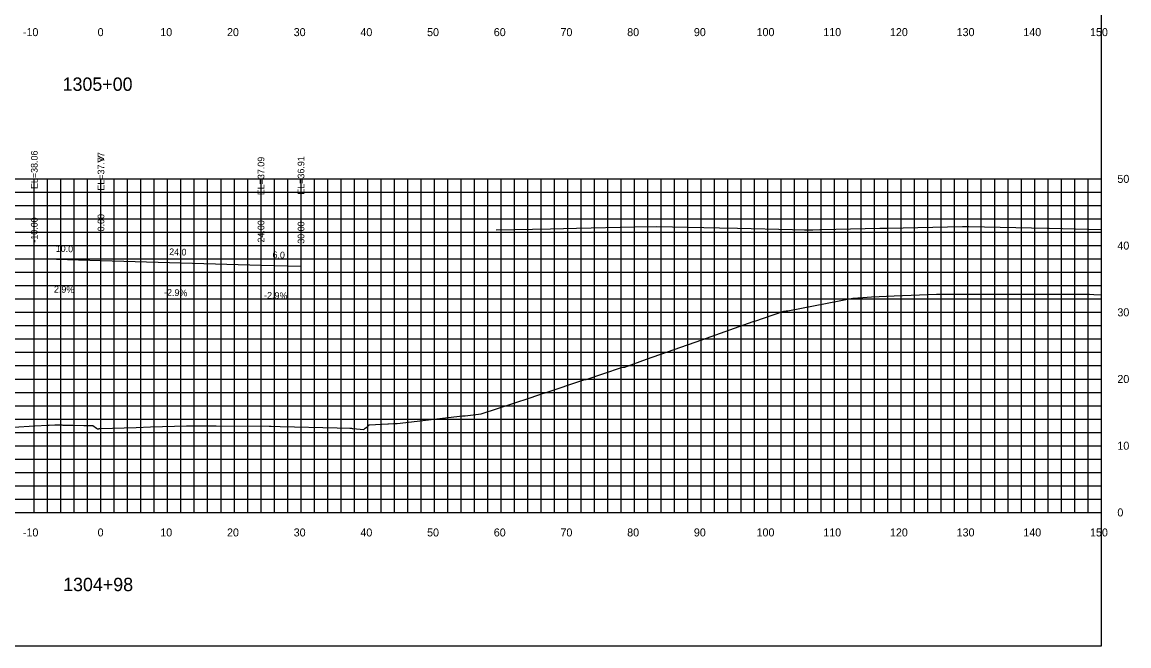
# Model space of a CAD drawing. Extents: x 1797714 to 1804825, y 249015 to 250269.
# Drawn here: x 1803952.3 to 1804118.3, y 249628.2 to 249721.7 of the extents above; entities that cross this region are included whole.
import ezdxf

# ---------------------------------------------------------------- set-up
doc = ezdxf.new("R2010")
doc.units = 0
for name, color, linetype in [('1', 7, 'Continuous'), ('10', 7, 'Continuous'), ('3', 7, 'Continuous'), ('31', 7, 'Continuous'), ('4', 7, 'Continuous'), ('60', 7, 'Continuous'), ('CL-CNST', 7, 'Continuous'), ('Level 62', 7, 'Continuous'), ('M-ROADS', 7, 'Continuous'), ('WEARING', 7, 'Continuous')]:
    doc.layers.add(name, color=color, linetype=linetype)

msp = doc.modelspace()

# ---------------------------------------------------------------- linework, layer by layer
for p, q in [((1803954.16, 249686.23), (1803954.16, 249688.23)), ((1803964.16, 249685.94), (1803964.16, 249687.94)), ((1803988.16, 249685.25), (1803988.16, 249687.25)), ((1803994.16, 249685.08), (1803994.16, 249687.08))]:
    msp.add_line(p, q)
msp.add_lwpolyline([(1803814.16, 249628.17), (1804114.16, 249628.17), (1804114.16, 249818.17), (1803814.16, 249818.17)], close=True)
at = {"layer": '60'}
for p, q in [((1804114.16, 249648.17), (1804114.16, 249698.17)), ((1804114.22, 249698.17), (1804114.16, 249698.17)), ((1804114.22, 249688.17), (1804114.16, 249688.17)), ((1804114.22, 249678.17), (1804114.16, 249678.17)), ((1804114.22, 249668.17), (1804114.16, 249668.17)), ((1804114.22, 249658.17), (1804114.16, 249658.17)), ((1803814.16, 249648.17), (1804114.16, 249648.17)), ((1803954.16, 249648.11), (1803954.16, 249648.17)), ((1803964.16, 249648.11), (1803964.16, 249648.17)), ((1803974.16, 249648.11), (1803974.16, 249648.17)), ((1803984.16, 249648.11), (1803984.16, 249648.17)), ((1803994.16, 249648.11), (1803994.16, 249648.17)), ((1804004.16, 249648.11), (1804004.16, 249648.17)), ((1804014.16, 249648.11), (1804014.16, 249648.17)), ((1804024.16, 249648.11), (1804024.16, 249648.17)), ((1804034.16, 249648.11), (1804034.16, 249648.17)), ((1804044.16, 249648.11), (1804044.16, 249648.17)), ((1804054.16, 249648.11), (1804054.16, 249648.17)), ((1804064.16, 249648.11), (1804064.16, 249648.17)), ((1804074.16, 249648.11), (1804074.16, 249648.17)), ((1804084.16, 249648.11), (1804084.16, 249648.17)), ((1804094.16, 249648.11), (1804094.16, 249648.17)), ((1804104.16, 249648.11), (1804104.16, 249648.17)), ((1804114.16, 249648.11), (1804114.16, 249648.17)), ((1804114.22, 249648.17), (1804114.16, 249648.17))]:
    msp.add_line(p, q, dxfattribs=at)
at = {"layer": 'CL-CNST'}
for points in [[(1804023.41, 249690.52), (1804031.56, 249690.7), (1804035.47, 249690.78), (1804044.23, 249690.97), (1804047.53, 249691.04), (1804056.91, 249690.83), (1804059.59, 249690.77), (1804067.85, 249690.59), (1804069.64, 249690.55), (1804070.69, 249690.52), (1804070.9, 249690.52)], [(1803954.16, 249686.23), (1803964.16, 249685.94), (1803988.16, 249685.25), (1803994.16, 249685.08)]]:
    msp.add_lwpolyline(points, dxfattribs=at)
at = {"layer": 'Level 62'}
for p, q in [((1803814.16, 249698.17), (1804114.16, 249698.17)), ((1803954.16, 249648.17), (1803954.16, 249698.17)), ((1803956.16, 249648.17), (1803956.16, 249698.17)), ((1803958.16, 249648.17), (1803958.16, 249698.17)), ((1803960.16, 249648.17), (1803960.16, 249698.17)), ((1803962.16, 249648.17), (1803962.16, 249698.17)), ((1803964.16, 249648.17), (1803964.16, 249698.17)), ((1803966.16, 249648.17), (1803966.16, 249698.17)), ((1803968.16, 249648.17), (1803968.16, 249698.17)), ((1803970.16, 249648.17), (1803970.16, 249698.17)), ((1803972.16, 249648.17), (1803972.16, 249698.17)), ((1803974.16, 249648.17), (1803974.16, 249698.17)), ((1803976.16, 249648.17), (1803976.16, 249698.17)), ((1803978.16, 249648.17), (1803978.16, 249698.17)), ((1803980.16, 249648.17), (1803980.16, 249698.17)), ((1803982.16, 249648.17), (1803982.16, 249698.17)), ((1803984.16, 249648.17), (1803984.16, 249698.17)), ((1803986.16, 249648.17), (1803986.16, 249698.17)), ((1803988.16, 249648.17), (1803988.16, 249698.17)), ((1803990.16, 249648.17), (1803990.16, 249698.17)), ((1803992.16, 249648.17), (1803992.16, 249698.17)), ((1803994.16, 249648.17), (1803994.16, 249698.17)), ((1803996.16, 249648.17), (1803996.16, 249698.17)), ((1803998.16, 249648.17), (1803998.16, 249698.17)), ((1804000.16, 249648.17), (1804000.16, 249698.17)), ((1804002.16, 249648.17), (1804002.16, 249698.17)), ((1804004.16, 249648.17), (1804004.16, 249698.17)), ((1804006.16, 249648.17), (1804006.16, 249698.17)), ((1804008.16, 249648.17), (1804008.16, 249698.17)), ((1804010.16, 249648.17), (1804010.16, 249698.17)), ((1804012.16, 249648.17), (1804012.16, 249698.17)), ((1804014.16, 249648.17), (1804014.16, 249698.17)), ((1804016.16, 249648.17), (1804016.16, 249698.17)), ((1804018.16, 249648.17), (1804018.16, 249698.17)), ((1804020.16, 249648.17), (1804020.16, 249698.17)), ((1804022.16, 249648.17), (1804022.16, 249698.17)), ((1804024.16, 249648.17), (1804024.16, 249698.17)), ((1804026.16, 249648.17), (1804026.16, 249698.17)), ((1804028.16, 249648.17), (1804028.16, 249698.17)), ((1804030.16, 249648.17), (1804030.16, 249698.17)), ((1804032.16, 249648.17), (1804032.16, 249698.17)), ((1804034.16, 249648.17), (1804034.16, 249698.17)), ((1804036.16, 249648.17), (1804036.16, 249698.17)), ((1804038.16, 249648.17), (1804038.16, 249698.17)), ((1804040.16, 249648.17), (1804040.16, 249698.17)), ((1804042.16, 249648.17), (1804042.16, 249698.17)), ((1804044.16, 249648.17), (1804044.16, 249698.17)), ((1804046.16, 249648.17), (1804046.16, 249698.17)), ((1804048.16, 249648.17), (1804048.16, 249698.17)), ((1804050.16, 249648.17), (1804050.16, 249698.17)), ((1804052.16, 249648.17), (1804052.16, 249698.17)), ((1804054.16, 249648.17), (1804054.16, 249698.17)), ((1804056.16, 249648.17), (1804056.16, 249698.17)), ((1804058.16, 249648.17), (1804058.16, 249698.17)), ((1804060.16, 249648.17), (1804060.16, 249698.17)), ((1804062.16, 249648.17), (1804062.16, 249698.17)), ((1804064.16, 249648.17), (1804064.16, 249698.17)), ((1804066.16, 249648.17), (1804066.16, 249698.17)), ((1804068.16, 249648.17), (1804068.16, 249698.17)), ((1804070.16, 249648.17), (1804070.16, 249698.17)), ((1804072.16, 249648.17), (1804072.16, 249698.17)), ((1804074.16, 249648.17), (1804074.16, 249698.17)), ((1804076.16, 249648.17), (1804076.16, 249698.17)), ((1804078.16, 249648.17), (1804078.16, 249698.17)), ((1804080.16, 249648.17), (1804080.16, 249698.17)), ((1804082.16, 249648.17), (1804082.16, 249698.17)), ((1804084.16, 249648.17), (1804084.16, 249698.17)), ((1804086.16, 249648.17), (1804086.16, 249698.17)), ((1804088.16, 249648.17), (1804088.16, 249698.17)), ((1804090.16, 249648.17), (1804090.16, 249698.17)), ((1804092.16, 249648.17), (1804092.16, 249698.17)), ((1804094.16, 249648.17), (1804094.16, 249698.17)), ((1804096.16, 249648.17), (1804096.16, 249698.17)), ((1804098.16, 249648.17), (1804098.16, 249698.17)), ((1804100.16, 249648.17), (1804100.16, 249698.17)), ((1804102.16, 249648.17), (1804102.16, 249698.17)), ((1804104.16, 249648.17), (1804104.16, 249698.17)), ((1804106.16, 249648.17), (1804106.16, 249698.17)), ((1804108.16, 249648.17), (1804108.16, 249698.17)), ((1804110.16, 249648.17), (1804110.16, 249698.17)), ((1804112.16, 249648.17), (1804112.16, 249698.17)), ((1804114.16, 249648.17), (1804114.16, 249698.17)), ((1803814.16, 249696.17), (1804114.16, 249696.17)), ((1803814.16, 249694.17), (1804114.16, 249694.17)), ((1803814.16, 249692.17), (1804114.16, 249692.17)), ((1803814.16, 249690.17), (1804114.16, 249690.17)), ((1803814.16, 249688.17), (1804114.16, 249688.17)), ((1803814.16, 249686.17), (1804114.16, 249686.17)), ((1803814.16, 249684.17), (1804114.16, 249684.17)), ((1803814.16, 249682.17), (1804114.16, 249682.17)), ((1803814.16, 249680.17), (1804114.16, 249680.17)), ((1803814.16, 249678.17), (1804114.16, 249678.17)), ((1803814.16, 249676.17), (1804114.16, 249676.17)), ((1803814.16, 249674.17), (1804114.16, 249674.17)), ((1803814.16, 249672.17), (1804114.16, 249672.17)), ((1803814.16, 249670.17), (1804114.16, 249670.17)), ((1803814.16, 249668.17), (1804114.16, 249668.17)), ((1803814.16, 249666.17), (1804114.16, 249666.17)), ((1803814.16, 249664.17), (1804114.16, 249664.17)), ((1803814.16, 249662.17), (1804114.16, 249662.17)), ((1803814.16, 249660.17), (1804114.16, 249660.17)), ((1803814.16, 249658.17), (1804114.16, 249658.17)), ((1803814.16, 249656.17), (1804114.16, 249656.17)), ((1803814.16, 249654.17), (1804114.16, 249654.17)), ((1803814.16, 249652.17), (1804114.16, 249652.17)), ((1803814.16, 249650.17), (1804114.16, 249650.17)), ((1803814.16, 249648.17), (1804114.16, 249648.17))]:
    msp.add_line(p, q, dxfattribs=at)
at = {"layer": 'M-ROADS'}
msp.add_lwpolyline([(1803951.12, 249660.96), (1803954.14, 249661.16), (1803954.25, 249661.17), (1803956.18, 249661.25), (1803956.42, 249661.26), (1803957.23, 249661.3), (1803957.3, 249661.3), (1803957.74, 249661.3), (1803958.3, 249661.28), (1803958.46, 249661.27), (1803959.9, 249661.23), (1803959.96, 249661.23), (1803961.6, 249661.22), (1803962.14, 249661.2), (1803962.95, 249661.19), (1803963.49, 249660.78), (1803963.59, 249660.72), (1803963.79, 249660.72), (1803963.8, 249660.72), (1803963.81, 249660.72), (1803963.83, 249660.72), (1803963.85, 249660.73), (1803963.87, 249660.73), (1803963.9, 249660.73), (1803963.94, 249660.73), (1803963.99, 249660.73), (1803964.05, 249660.74), (1803964.11, 249660.74), (1803969.44, 249660.92), (1803971.58, 249660.99), (1803976.98, 249661.17), (1803977.33, 249661.16), (1803977.39, 249661.16), (1803981.45, 249661.14), (1803989.39, 249661.1), (1803989.69, 249661.09), (1803991.04, 249661.06), (1803999.58, 249660.85), (1804001.5, 249660.8), (1804001.61, 249660.79), (1804001.73, 249660.78), (1804001.83, 249660.77), (1804001.93, 249660.76), (1804003.56, 249660.59), (1804003.78, 249660.78), (1804004.16, 249661.06), (1804004.26, 249661.19), (1804004.37, 249661.28), (1804004.4, 249661.29), (1804007.17, 249661.43), (1804007.28, 249661.44), (1804008.02, 249661.5), (1804008.47, 249661.5), (1804008.56, 249661.5), (1804018.37, 249662.64), (1804018.47, 249662.65), (1804018.78, 249662.64), (1804021.15, 249662.94), (1804028.53, 249665.35), (1804030.66, 249666.08), (1804030.77, 249666.08), (1804036.58, 249668.06), (1804036.89, 249668.08), (1804042.19, 249669.92), (1804042.49, 249669.93), (1804042.7, 249669.93), (1804045.94, 249671.13), (1804054.25, 249674.04), (1804061.96, 249676.78), (1804062.06, 249676.78), (1804066.56, 249678.35), (1804066.92, 249678.37), (1804067.14, 249678.38), (1804076.88, 249680.28), (1804078.37, 249680.4), (1804079.7, 249680.51), (1804083.09, 249680.63), (1804089.42, 249680.89), (1804094.01, 249680.9), (1804100.81, 249680.9), (1804109.34, 249680.9), (1804112.39, 249680.9), (1804113.05, 249680.85), (1804114.16, 249680.77)], dxfattribs=at)
at = {"layer": 'WEARING'}
msp.add_lwpolyline([(1804070.9, 249690.55), (1804071.95, 249690.57), (1804072.16, 249690.57), (1804080.94, 249690.76), (1804082.21, 249690.79), (1804093.35, 249691.02), (1804094.27, 249691.04), (1804106.02, 249690.78), (1804106.33, 249690.77), (1804112.29, 249690.64), (1804114.16, 249690.6)], dxfattribs=at)

# ---------------------------------------------------------------- texts
at = {"layer": '1'}
for s, p in [('1305+00', (1803958.41, 249711.37)), ('1304+98', (1803958.49, 249636.37))]:
    msp.add_text(s, height=2, dxfattribs=at).set_placement(p)
at = {"layer": '10'}
for s, p in [('-10', (1803952.46, 249719.57)), ('0', (1803963.66, 249719.57)), ('10', (1803973.06, 249719.57)), ('20', (1803983.06, 249719.57)), ('30', (1803993.06, 249719.57)), ('40', (1804003.06, 249719.57)), ('50', (1804013.06, 249719.57)), ('60', (1804023.06, 249719.57)), ('70', (1804033.06, 249719.57)), ('80', (1804043.06, 249719.57)), ('90', (1804053.06, 249719.57)), ('100', (1804062.46, 249719.57)), ('110', (1804072.46, 249719.57)), ('120', (1804082.46, 249719.57)), ('130', (1804092.46, 249719.57)), ('140', (1804102.46, 249719.57)), ('150', (1804112.46, 249719.57)), ('-10', (1803952.46, 249644.57)), ('0', (1803963.66, 249644.57)), ('10', (1803973.06, 249644.57)), ('20', (1803983.06, 249644.57)), ('30', (1803993.06, 249644.57)), ('40', (1804003.06, 249644.57)), ('50', (1804013.06, 249644.57)), ('60', (1804023.06, 249644.57)), ('70', (1804033.06, 249644.57)), ('80', (1804043.06, 249644.57)), ('90', (1804053.06, 249644.57)), ('100', (1804062.46, 249644.57)), ('110', (1804072.46, 249644.57)), ('120', (1804082.46, 249644.57)), ('130', (1804092.46, 249644.57)), ('140', (1804102.46, 249644.57)), ('150', (1804112.46, 249644.57))]:
    msp.add_text(s, height=1.2, dxfattribs=at).set_placement(p)
at = {"layer": '3'}
for s, p in [('EL=38.06', (1803954.66, 249696.65)), ('EL=37.77', (1803964.66, 249696.41)), ('EL=37.09', (1803988.66, 249695.72)), ('EL=36.91', (1803994.66, 249695.8)), ('-10.00', (1803954.66, 249688.61)), ('0.00', (1803964.66, 249690.3)), ('24.00', (1803988.66, 249688.62)), ('30.00', (1803994.66, 249688.45))]:
    msp.add_text(s, height=1, rotation=90, dxfattribs=at).set_placement(p)
at = {"layer": '31'}
for s, p in [('50', (1804116.56, 249697.57)), ('40', (1804116.56, 249687.57)), ('30', (1804116.56, 249677.57)), ('20', (1804116.56, 249667.57)), ('10', (1804116.56, 249657.57)), ('0', (1804116.56, 249647.57))]:
    msp.add_text(s, height=1.2, dxfattribs=at).set_placement(p)
at = {"layer": '4'}
for s, p in [('10.0', (1803957.37, 249687.24)), ('24.0', (1803974.37, 249686.75)), ('6.0', (1803989.87, 249686.3)), ('2.9%', (1803957.1, 249681.14)), ('-2.9%', (1803973.61, 249680.67)), ('-2.9%', (1803988.61, 249680.24))]:
    msp.add_text(s, height=1, rotation=358.3574, dxfattribs=at).set_placement(p)
at = {"layer": '60'}
msp.add_text('>', height=1.5, dxfattribs=at).set_placement((1803963.55, 249700.42))

doc.saveas('drawing.dxf')
